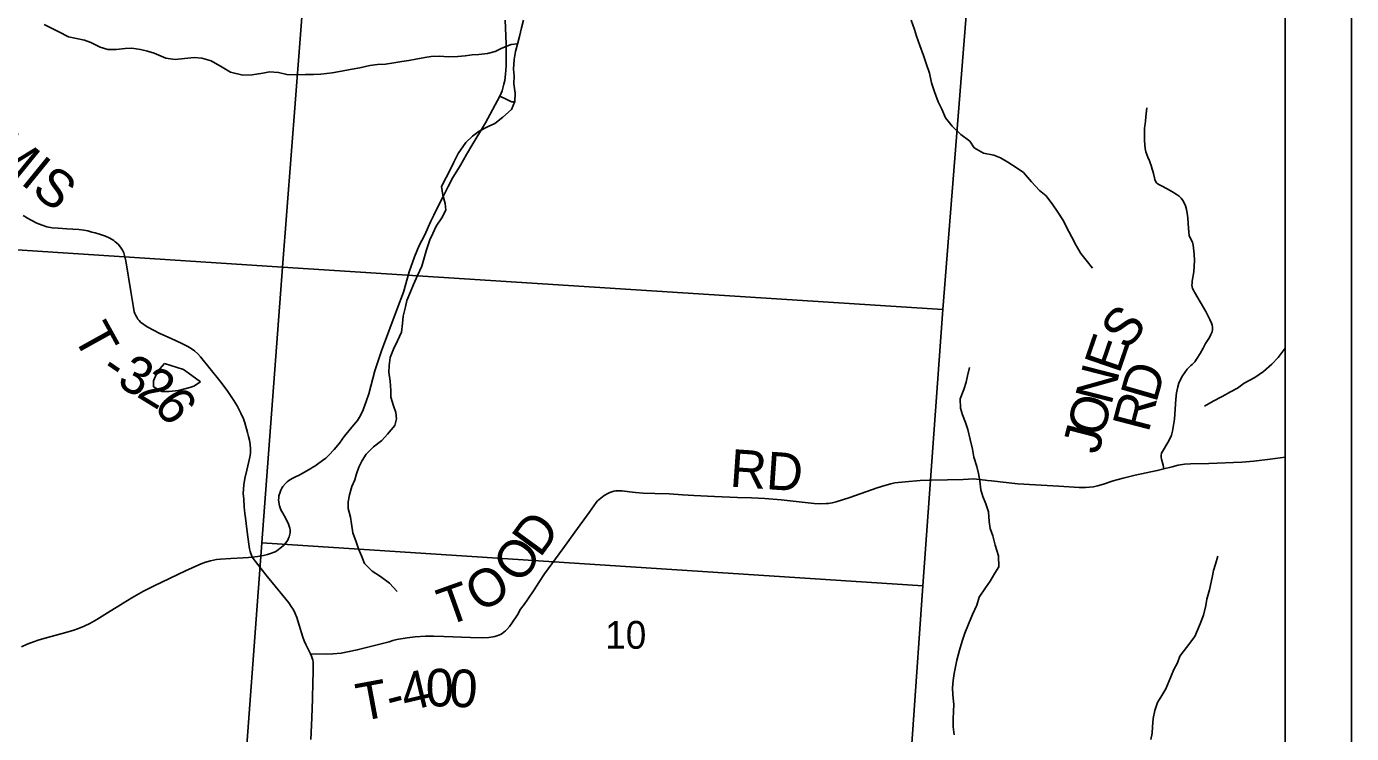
# Model space of a CAD drawing. Extents: x 0 to 34, y 0 to 22.
# Drawn here: x 6.999 to 9, y 15.952 to 17.019 of the extents above; entities that cross this region are included whole.
import ezdxf

# ---------------------------------------------------------------- set-up
doc = ezdxf.new("R2010")
doc.units = 0
for name, color, linetype in [('GM_X_Corporation', 7, 'Continuous'), ('GM_X_County_Road', 7, 'Continuous'), ('GM_X_Minor_Lake', 7, 'Continuous'), ('GM_X_Minor_River', 7, 'Continuous'), ('GM_X_Section_Text', 7, 'Continuous'), ('GM_X_Township_Road', 7, 'Continuous'), ('GM_X_Township_Road_Text', 7, 'Continuous'), ('SH_Data', 7, 'Continuous')]:
    doc.layers.add(name, color=color, linetype=linetype)

msp = doc.modelspace()

# ---------------------------------------------------------------- linework, layer by layer
at = {"layer": 'GM_X_Corporation'}
for points in [[(6.4386, 17.7441), (7.4643, 17.6703), (7.3858, 16.6558), (6.3912, 16.7203)], [(8.4629, 17.601), (8.3827, 16.5919), (7.3858, 16.6558), (7.4643, 17.6703)], [(6.3912, 16.7203), (7.3858, 16.6558), (7.3548, 16.2394), (7.3238, 15.8259), (7.3098, 15.6422), (6.7101, 15.6799), (6.3225, 15.705), (6.3352, 15.898), (6.3636, 16.3035)], [(8.3827, 16.5919), (8.3529, 16.1745), (7.3548, 16.2394), (7.3858, 16.6558)], [(8.3529, 16.1745), (8.3234, 15.756), (7.3238, 15.8259), (7.3548, 16.2394)]]:
    msp.add_lwpolyline(points, close=True, dxfattribs=at)
at = {"layer": 'GM_X_County_Road'}
msp.add_lwpolyline([(6.9919, 16.0824), (7.0002, 16.0865), (7.0098, 16.0902), (7.0186, 16.0931), (7.0365, 16.0982), (7.0533, 16.1024), (7.0694, 16.1071), (7.0781, 16.1102), (7.0866, 16.1137), (7.095, 16.1177), (7.1057, 16.1238), (7.1215, 16.1336), (7.1452, 16.1485), (7.1585, 16.1565), (7.1761, 16.1664), (7.192, 16.1744), (7.2395, 16.1973), (7.2594, 16.2062), (7.2681, 16.2095), (7.2771, 16.2122), (7.2863, 16.2142), (7.2925, 16.215), (7.308, 16.2159), (7.3266, 16.2167), (7.3347, 16.2173), (7.34, 16.2178), (7.3482, 16.2188), (7.3573, 16.2205), (7.3633, 16.2219), (7.3691, 16.2237), (7.372, 16.2248), (7.3747, 16.2261), (7.3774, 16.2276), (7.38, 16.2293), (7.3825, 16.2313), (7.3846, 16.233), (7.3876, 16.2355), (7.3905, 16.2388), (7.3937, 16.2436), (7.395, 16.2463), (7.396, 16.2486), (7.3976, 16.2546), (7.3975, 16.2589), (7.3969, 16.2618), (7.3948, 16.2676), (7.3909, 16.276), (7.3865, 16.2841), (7.3836, 16.2895), (7.3823, 16.2923), (7.3814, 16.2951), (7.3803, 16.301), (7.38, 16.3042), (7.3801, 16.3074), (7.3806, 16.3106), (7.3822, 16.316), (7.3834, 16.3191), (7.3849, 16.3219), (7.3866, 16.3245), (7.3904, 16.3292), (7.3929, 16.3314), (7.3953, 16.3334), (7.4007, 16.3367), (7.4064, 16.3396), (7.4098, 16.3413), (7.4155, 16.3441), (7.4287, 16.3519), (7.4317, 16.3537), (7.4345, 16.3554), (7.4387, 16.358), (7.4464, 16.3635), (7.4514, 16.3675), (7.4557, 16.3716), (7.4641, 16.3805), (7.4719, 16.39), (7.4792, 16.4), (7.4932, 16.4169), (7.499, 16.4242), (7.5024, 16.4293), (7.5054, 16.4345), (7.5078, 16.44), (7.5088, 16.443), (7.5098, 16.4456), (7.5127, 16.4544), (7.5163, 16.4646), (7.5251, 16.499), (7.5352, 16.5293), (7.559, 16.5928), (7.5684, 16.6177), (7.577, 16.6484), (7.5853, 16.6711), (7.5922, 16.6881), (7.6002, 16.7035), (7.61, 16.725), (7.6142, 16.7343), (7.62, 16.7457), (7.6278, 16.7611), (7.6361, 16.7775), (7.6433, 16.7907), (7.6492, 16.8004), (7.6532, 16.8071), (7.6547, 16.8097), (7.6635, 16.8258), (7.6731, 16.8417), (7.6893, 16.8685), (7.6922, 16.8736), (7.7138, 16.9138), (7.7159, 16.918), (7.7174, 16.9219), (7.7203, 16.9316), (7.7216, 16.9376), (7.7227, 16.9468), (7.7234, 16.9592), (7.7237, 16.9746), (7.7234, 16.9925), (7.7223, 17.0287)], dxfattribs=at)
at = {"layer": 'GM_X_Minor_Lake'}
for p, q in [((7.2077, 16.5101), (7.1972, 16.4979)), ((7.2362, 16.5013), (7.2077, 16.5101)), ((7.1972, 16.4979), (7.1909, 16.4842)), ((7.2488, 16.4919), (7.2362, 16.5013)), ((7.2621, 16.4826), (7.2488, 16.4919)), ((7.1909, 16.4842), (7.191, 16.4747)), ((7.191, 16.4747), (7.2039, 16.468)), ((7.2039, 16.468), (7.2149, 16.4678)), ((7.2149, 16.4678), (7.2289, 16.4694)), ((7.2289, 16.4694), (7.2459, 16.4741)), ((7.2459, 16.4741), (7.2519, 16.4761)), ((7.2519, 16.4761), (7.2621, 16.4826))]:
    msp.add_line(p, q, dxfattribs=at)
at = {"layer": 'GM_X_Minor_River'}
for p, q in [((8.3353, 17.0286), (8.34, 17.0146)), ((7.038, 17.016), (7.0258, 17.0219)), ((7.0482, 17.0108), (7.038, 17.016)), ((7.0627, 17.0033), (7.0482, 17.0108)), ((8.34, 17.0146), (8.3431, 17.0044)), ((7.0725, 17.0015), (7.0627, 17.0033)), ((7.0869, 16.9982), (7.0725, 17.0015)), ((7.0964, 16.9949), (7.0869, 16.9982)), ((7.1105, 16.9878), (7.0964, 16.9949)), ((7.1219, 16.9842), (7.1105, 16.9878)), ((7.1586, 16.986), (7.1484, 16.9855)), ((7.1714, 16.9842), (7.1586, 16.986)), ((7.717, 16.9862), (7.7069, 16.9812)), ((7.731, 16.9916), (7.717, 16.9862)), ((7.7408, 16.9927), (7.731, 16.9916)), ((8.3431, 17.0044), (8.3481, 16.9904)), ((8.3481, 16.9904), (8.3536, 16.9749)), ((7.1347, 16.9843), (7.1219, 16.9842)), ((7.1484, 16.9855), (7.1347, 16.9843)), ((7.1821, 16.9817), (7.1714, 16.9842)), ((7.1923, 16.9784), (7.1821, 16.9817)), ((7.2098, 16.9713), (7.1923, 16.9784)), ((7.2238, 16.9692), (7.2098, 16.9713)), ((7.2378, 16.9708), (7.2238, 16.9692)), ((7.2525, 16.9721), (7.2378, 16.9708)), ((7.2639, 16.971), (7.2525, 16.9721)), ((7.2783, 16.967), (7.2639, 16.971)), ((7.295, 16.9573), (7.2783, 16.967)), ((7.5659, 16.9662), (7.5538, 16.9638)), ((7.5768, 16.9678), (7.5659, 16.9662)), ((7.5874, 16.9695), (7.5768, 16.9678)), ((7.6006, 16.9722), (7.5874, 16.9695)), ((7.6104, 16.9738), (7.6006, 16.9722)), ((7.6229, 16.9743), (7.6104, 16.9738)), ((7.6362, 16.9733), (7.6229, 16.9743)), ((7.6506, 16.9738), (7.6362, 16.9733)), ((7.6619, 16.9747), (7.6506, 16.9738)), ((7.6721, 16.9759), (7.6619, 16.9747)), ((7.6823, 16.9768), (7.6721, 16.9759)), ((7.6952, 16.978), (7.6823, 16.9768)), ((7.7069, 16.9812), (7.6952, 16.978)), ((8.3536, 16.9749), (8.3578, 16.9632)), ((7.3076, 16.9498), (7.295, 16.9573)), ((7.3262, 16.9455), (7.3076, 16.9498)), ((7.3402, 16.946), (7.3262, 16.9455)), ((7.356, 16.9484), (7.3402, 16.946)), ((7.3662, 16.9504), (7.356, 16.9484)), ((7.3798, 16.9497), (7.3662, 16.9504)), ((7.3924, 16.9465), (7.3798, 16.9497)), ((7.4083, 16.9458), (7.3924, 16.9465)), ((7.4204, 16.9463), (7.4083, 16.9458)), ((7.4328, 16.9464), (7.4204, 16.9463)), ((7.4438, 16.9469), (7.4328, 16.9464)), ((7.4608, 16.949), (7.4438, 16.9469)), ((7.4748, 16.9514), (7.4608, 16.949)), ((7.488, 16.9541), (7.4748, 16.9514)), ((7.5028, 16.9566), (7.488, 16.9541)), ((7.5179, 16.9601), (7.5028, 16.9566)), ((7.5292, 16.9617), (7.5179, 16.9601)), ((7.5413, 16.9622), (7.5292, 16.9617)), ((7.5538, 16.9638), (7.5413, 16.9622)), ((8.3578, 16.9632), (8.3629, 16.9485)), ((8.3629, 16.9485), (8.366, 16.9337)), ((8.366, 16.9337), (8.3703, 16.9205)), ((8.3703, 16.9205), (8.3757, 16.905)), ((8.3757, 16.905), (8.3815, 16.8941)), ((8.3815, 16.8941), (8.3869, 16.8812)), ((8.3869, 16.8812), (8.3969, 16.8685)), ((8.3969, 16.8685), (8.4102, 16.8561)), ((8.4102, 16.8561), (8.4235, 16.8456)), ((8.4235, 16.8456), (8.4304, 16.8358)), ((8.4304, 16.8358), (8.4445, 16.8276)), ((8.4445, 16.8276), (8.4601, 16.8247)), ((8.4601, 16.8247), (8.4699, 16.8206)), ((8.4699, 16.8206), (8.481, 16.8143)), ((8.481, 16.8143), (8.495, 16.8049)), ((8.495, 16.8049), (8.5049, 16.7986)), ((8.5049, 16.7986), (8.5168, 16.7843)), ((8.5168, 16.7843), (8.529, 16.7715)), ((8.529, 16.7715), (8.5389, 16.7633)), ((8.5389, 16.7633), (8.5492, 16.7497)), ((8.5492, 16.7497), (8.5558, 16.7399)), ((8.5558, 16.7399), (8.5653, 16.7256)), ((8.5653, 16.7256), (8.5696, 16.7158)), ((8.5696, 16.7158), (8.5777, 16.7007)), ((8.5777, 16.7007), (8.5842, 16.6883)), ((8.5842, 16.6883), (8.5915, 16.6762)), ((8.5915, 16.6762), (8.5992, 16.666)), ((8.5992, 16.666), (8.6091, 16.654)), ((8.8996, 16.5331), (8.8891, 16.5194)), ((8.9, 16.5336), (8.8996, 16.5331)), ((8.8798, 16.5091), (8.867, 16.498)), ((8.8891, 16.5194), (8.8798, 16.5091)), ((8.8542, 16.4888), (8.838, 16.4807)), ((8.867, 16.498), (8.8542, 16.4888)), ((8.8173, 16.4672), (8.8045, 16.4603)), ((8.8278, 16.473), (8.8173, 16.4672)), ((8.838, 16.4807), (8.8278, 16.473)), ((8.7909, 16.4533), (8.7781, 16.446)), ((8.8045, 16.4603), (8.7909, 16.4533)), ((8.7916, 16.1976), (8.7946, 16.2071)), ((8.7946, 16.2071), (8.7983, 16.2192)), ((8.7855, 16.1683), (8.7898, 16.1873)), ((8.7898, 16.1873), (8.7916, 16.1976)), ((8.7818, 16.1546), (8.7855, 16.1683)), ((8.78, 16.1448), (8.7818, 16.1546)), ((8.7715, 16.1174), (8.7763, 16.13)), ((8.7763, 16.13), (8.78, 16.1448)), ((8.7634, 16.098), (8.7675, 16.1075)), ((8.7675, 16.1075), (8.7715, 16.1174)), ((8.751, 16.0816), (8.7634, 16.098)), ((8.7372, 16.0584), (8.7409, 16.0686)), ((8.7409, 16.0686), (8.751, 16.0816)), ((8.7272, 16.0374), (8.7316, 16.0481)), ((8.7316, 16.0481), (8.7372, 16.0584)), ((8.7198, 16.0192), (8.7272, 16.0374)), ((8.7071, 15.9986), (8.7138, 16.0089)), ((8.7138, 16.0089), (8.7198, 16.0192)), ((8.7005, 15.9743), (8.703, 15.9861)), ((8.703, 15.9861), (8.7071, 15.9986)), ((8.6995, 15.9618), (8.7005, 15.9743)), ((8.697, 15.9424), (8.6988, 15.9523)), ((8.6988, 15.9523), (8.6995, 15.9618))]:
    msp.add_line(p, q, dxfattribs=at)
for points in [[(7.7496, 17.0285), (7.7467, 17.0171), (7.7438, 17.0038), (7.7412, 16.9943), (7.7379, 16.9814), (7.7357, 16.9689), (7.7347, 16.9545), (7.7356, 16.9443), (7.7353, 16.9321), (7.7373, 16.9185), (7.7367, 16.9056), (7.7318, 16.8935), (7.7187, 16.882), (7.7063, 16.8724), (7.6965, 16.8681), (7.6826, 16.8608), (7.6728, 16.8531), (7.6627, 16.8436), (7.6511, 16.8272), (7.6444, 16.8142), (7.6399, 16.8043), (7.6328, 16.791), (7.6262, 16.7773), (7.6278, 16.7641), (7.6317, 16.7516), (7.6325, 16.7417), (7.6266, 16.7303), (7.618, 16.7177), (7.6131, 16.7063), (7.6083, 16.6968), (7.6031, 16.6816), (7.5995, 16.6675), (7.5962, 16.6573), (7.5895, 16.6432), (7.5835, 16.6295), (7.5791, 16.6185), (7.5735, 16.6055), (7.5714, 16.5957), (7.5681, 16.5816), (7.567, 16.5703), (7.5656, 16.5574), (7.5593, 16.5444), (7.5534, 16.5319), (7.5486, 16.5193), (7.5468, 16.5072), (7.5465, 16.4973), (7.5485, 16.4837)], [(8.4003, 15.9496), (8.3987, 15.9617), (8.3986, 15.9731), (8.3992, 15.9852), (8.3995, 15.9954), (8.3979, 16.0102), (8.3974, 16.0204), (8.3984, 16.0318), (8.3999, 16.0424), (8.402, 16.0523), (8.4039, 16.0625), (8.4079, 16.0773), (8.4119, 16.091), (8.416, 16.1032), (8.4215, 16.1169), (8.4275, 16.1313), (8.4342, 16.1454), (8.4378, 16.1572), (8.4476, 16.1713), (8.4543, 16.1816), (8.4617, 16.1934), (8.4673, 16.2033), (8.4668, 16.22), (8.4618, 16.2358), (8.4582, 16.2498), (8.4543, 16.2612), (8.4531, 16.2714), (8.4519, 16.2862), (8.448, 16.2982), (8.4433, 16.3096), (8.4402, 16.3194), (8.4386, 16.333), (8.437, 16.344), (8.4342, 16.3546), (8.4296, 16.3686), (8.4276, 16.381), (8.424, 16.3954), (8.4209, 16.4105), (8.417, 16.4211), (8.4127, 16.4328), (8.4096, 16.4427), (8.4091, 16.457), (8.4147, 16.4711), (8.4184, 16.4818), (8.4202, 16.4916), (8.4231, 16.5042)], [(7.5485, 16.4837), (7.5494, 16.4693), (7.5495, 16.4594), (7.5534, 16.4462), (7.5568, 16.4364), (7.5581, 16.4266), (7.5555, 16.4167), (7.5446, 16.4037), (7.536, 16.3938), (7.5232, 16.3842), (7.5124, 16.3735), (7.506, 16.3636), (7.5012, 16.3537), (7.4975, 16.3438), (7.4949, 16.3343), (7.4908, 16.3244), (7.4868, 16.3118), (7.485, 16.3012), (7.4851, 16.2914), (7.4886, 16.2781), (7.4902, 16.2679), (7.4922, 16.2547), (7.4969, 16.2411), (7.5007, 16.2305), (7.505, 16.2199), (7.5096, 16.2082), (7.5211, 16.1966), (7.534, 16.1887), (7.5474, 16.1783), (7.5592, 16.1659)]]:
    msp.add_lwpolyline(points, dxfattribs=at)
at = {"layer": 'GM_X_Township_Road'}
for points in [[(7.736, 16.9052), (7.7336, 16.9052), (7.7321, 16.9054), (7.7306, 16.9058), (7.7277, 16.907), (7.7234, 16.909), (7.7138, 16.9138)], [(8.7596, 16.5088), (8.7633, 16.5129), (8.7672, 16.5184), (8.7714, 16.5254), (8.7758, 16.5334), (8.7798, 16.5405), (8.7854, 16.5496), (8.7877, 16.554), (8.7894, 16.558), (8.7901, 16.5613), (8.7901, 16.5648), (8.7894, 16.568), (8.7884, 16.5712), (8.7862, 16.5768), (8.7836, 16.5818), (8.78, 16.5885), (8.7629, 16.618), (8.7612, 16.6208), (8.7599, 16.6234), (8.7592, 16.6259), (8.759, 16.6286), (8.7593, 16.6316), (8.7596, 16.6344), (8.7617, 16.6483), (8.7626, 16.6573), (8.7627, 16.6658), (8.7622, 16.6751), (8.7609, 16.6889), (8.76, 16.6931), (8.7568, 16.6987), (8.755, 16.7035), (8.7543, 16.7083), (8.7535, 16.7213), (8.7531, 16.7303), (8.7521, 16.7371), (8.7509, 16.7425), (8.7492, 16.7481), (8.7474, 16.7526), (8.7453, 16.7564), (8.7428, 16.7599), (8.7397, 16.7628), (8.7352, 16.766), (8.7285, 16.77), (8.7209, 16.7741), (8.714, 16.7777), (8.7082, 16.7808), (8.7058, 16.7831), (8.7043, 16.7852), (8.7031, 16.7879), (8.7023, 16.7906), (8.7008, 16.7969), (8.6999, 16.8005), (8.699, 16.8037), (8.6974, 16.809), (8.696, 16.813), (8.6949, 16.8162), (8.6924, 16.8215), (8.6908, 16.8257), (8.6896, 16.8297), (8.6887, 16.8348), (8.6879, 16.8402), (8.6874, 16.8468), (8.6873, 16.8536), (8.6874, 16.8599), (8.6876, 16.8651), (8.6879, 16.869), (8.6883, 16.8722), (8.6888, 16.8759), (8.6897, 16.8823), (8.6911, 16.896)], [(7.34, 16.2178), (7.3369, 16.2262), (7.3363, 16.2302), (7.3331, 16.2521), (7.331, 16.2685), (7.3299, 16.277), (7.329, 16.2836), (7.328, 16.294), (7.3273, 16.3054), (7.3267, 16.3141), (7.3269, 16.3204), (7.3276, 16.3268), (7.3292, 16.3368), (7.3322, 16.3491), (7.3367, 16.3688), (7.3375, 16.3749), (7.3376, 16.3815), (7.337, 16.388), (7.336, 16.3945), (7.3347, 16.4002), (7.3332, 16.406), (7.3289, 16.4208), (7.3268, 16.4266), (7.323, 16.4351), (7.3173, 16.4461), (7.3123, 16.4543), (7.3023, 16.4693), (7.2912, 16.4841), (7.2621, 16.5204), (7.2578, 16.5249), (7.2532, 16.5291), (7.2482, 16.5327), (7.2429, 16.5359), (7.2318, 16.5415), (7.2177, 16.5479), (7.2006, 16.5554), (7.1814, 16.5654), (7.1763, 16.5689), (7.1715, 16.5728), (7.1693, 16.575), (7.1674, 16.5773), (7.1657, 16.5799), (7.1642, 16.5826), (7.163, 16.5854), (7.1621, 16.5884), (7.1603, 16.5976), (7.1569, 16.619), (7.1494, 16.6653), (7.1473, 16.6734), (7.1462, 16.6771), (7.1441, 16.6813), (7.1411, 16.6859), (7.1376, 16.6902), (7.1334, 16.6939), (7.1311, 16.6958), (7.1286, 16.6975), (7.124, 16.6999), (7.1184, 16.7024), (7.1127, 16.7043), (7.1028, 16.7072), (7.0981, 16.7085), (7.0919, 16.7102), (7.0859, 16.7114), (7.0783, 16.7124), (7.0603, 16.7135), (7.0472, 16.7143), (7.0381, 16.7152), (7.03, 16.7167), (7.0231, 16.7188), (7.015, 16.7218), (7.0062, 16.7265), (7.0007, 16.7294), (6.9943, 16.7335)], [(8.7167, 16.3512), (8.7155, 16.3567), (8.7131, 16.3656), (8.7125, 16.3687), (8.7125, 16.3718), (8.7133, 16.3747), (8.7147, 16.3775), (8.7228, 16.3907), (8.7257, 16.3962), (8.728, 16.4019), (8.7298, 16.4079), (8.7308, 16.414), (8.7325, 16.426), (8.7346, 16.4565), (8.7358, 16.4658), (8.7376, 16.4747), (8.7393, 16.4805), (8.7417, 16.4862), (8.7447, 16.4916), (8.7482, 16.4966), (8.7521, 16.5014), (8.7549, 16.5044), (8.7574, 16.507), (8.7596, 16.5088)], [(7.4284, 16.0718), (7.4529, 16.0713), (7.4621, 16.0718), (7.4744, 16.0731), (7.4866, 16.0752), (7.4987, 16.0778), (7.5468, 16.0901), (7.5527, 16.0919), (7.5587, 16.0933), (7.5739, 16.0959), (7.5862, 16.0975), (7.6016, 16.0984), (7.6139, 16.0985), (7.6294, 16.0982), (7.6697, 16.0964), (7.6882, 16.0961), (7.6975, 16.0965), (7.7036, 16.0973), (7.7065, 16.0979), (7.7094, 16.0989), (7.7123, 16.1), (7.715, 16.1012), (7.7176, 16.1027), (7.7202, 16.1044), (7.7225, 16.1064), (7.7247, 16.1084), (7.7287, 16.113), (7.7323, 16.118), (7.7405, 16.1309), (7.7455, 16.1391), (7.7509, 16.1465), (7.7562, 16.1542), (7.7659, 16.1686), (7.7728, 16.1797), (7.7817, 16.1926), (7.8091, 16.2304), (7.8271, 16.2557), (7.8488, 16.2854), (7.8559, 16.2955), (7.8597, 16.3004), (7.8617, 16.3028), (7.864, 16.305), (7.8664, 16.3071), (7.8689, 16.3091), (7.8716, 16.3109), (7.8772, 16.314), (7.8801, 16.3153), (7.883, 16.3163), (7.886, 16.3172), (7.8892, 16.3177), (7.8924, 16.3179), (7.8986, 16.3178), (7.9096, 16.3164), (7.9191, 16.3154), (7.9303, 16.3145), (7.9482, 16.314), (7.9696, 16.3133), (7.9899, 16.312), (8.0071, 16.3108), (8.0384, 16.3092), (8.0727, 16.308), (8.0938, 16.3075), (8.114, 16.3066), (8.1389, 16.3042), (8.1886, 16.2988), (8.1978, 16.2984), (8.207, 16.2987), (8.21, 16.2988), (8.216, 16.2998), (8.222, 16.3012), (8.2426, 16.3079), (8.2836, 16.3223), (8.2955, 16.3262), (8.3046, 16.3286), (8.3107, 16.3298), (8.3261, 16.3317), (8.3488, 16.3337), (8.363, 16.334), (8.3902, 16.3346), (8.4137, 16.3352), (8.4296, 16.3358), (8.4421, 16.3347), (8.4471, 16.3341), (8.4506, 16.3337), (8.4562, 16.333), (8.496, 16.3286), (8.558, 16.3248), (8.589, 16.3231), (8.5983, 16.323), (8.6044, 16.3233), (8.6105, 16.3241), (8.6165, 16.3255), (8.6254, 16.3281), (8.6402, 16.3329), (8.6552, 16.3371), (8.6734, 16.3414), (8.7067, 16.3484), (8.7167, 16.3512), (8.7294, 16.3544), (8.7384, 16.3565), (8.7476, 16.358), (8.7568, 16.3585), (8.7847, 16.359), (8.8342, 16.3612), (8.8527, 16.3627), (8.8773, 16.3655), (8.9, 16.3687)], [(7.4287, 15.9423), (7.43, 15.9753), (7.4311, 16.0041), (7.4315, 16.0289), (7.4321, 16.0436), (7.4323, 16.056), (7.432, 16.0591), (7.4315, 16.0621), (7.4309, 16.0651), (7.4299, 16.0681), (7.4284, 16.0718), (7.4212, 16.0861), (7.4186, 16.0916), (7.4165, 16.0972), (7.4113, 16.115), (7.4075, 16.1268), (7.4051, 16.1326), (7.4023, 16.1382), (7.3991, 16.1435), (7.3955, 16.1487), (7.3864, 16.16), (7.3632, 16.1879), (7.3536, 16.2), (7.34, 16.2178)]]:
    msp.add_lwpolyline(points, dxfattribs=at)
at = {"layer": 'SH_Data'}
for p, q in [((9, 21), (9, 14)), ((8.9, 20.9), (8.9, 14.1))]:
    msp.add_line(p, q, dxfattribs=at)

# ---------------------------------------------------------------- texts
at = {"layer": 'GM_X_Section_Text'}
msp.add_text('10', height=0.04186, rotation=0, dxfattribs=at).set_placement((7.873, 16.0796))
at = {"layer": 'GM_X_Township_Road_Text'}
for s, height, rotation, p in [('LOOMIS', 0.05682, 320.8393, (6.8152, 16.924)), ('S', 0.0568, 49.3822, (8.6602, 16.5285)), ('T', 0.0568, 299.0209, (7.0686, 16.5521)), ('E', 0.0568, 71.0568, (8.6492, 16.4932)), ('-', 0.0568, 325.4317, (7.1082, 16.494)), ('3', 0.0568, 332.3256, (7.1338, 16.4769)), ('N', 0.0568, 75.5632, (8.6371, 16.4459)), ('D', 0.0568, 73.9825, (8.705, 16.4493)), ('2', 0.0568, 328.4106, (7.1639, 16.4612)), ('6', 0.0568, 307.3268, (7.1897, 16.4465)), ('O', 0.0568, 75.5529, (8.6246, 16.3975)), ('R', 0.0568, 75.4336, (8.6934, 16.4045)), ('J', 0.0568, 75.5579, (8.6179, 16.3716)), ('RD', 0.05682, 356.0553, (8.0603, 16.3244)), ('D', 0.0568, 53.8521, (7.7747, 16.2156)), ('O', 0.0568, 54.0332, (7.7454, 16.1751)), ('O', 0.0568, 30.9231, (7.6841, 16.1327)), ('T', 0.0568, 19.625, (7.6331, 16.1132)), ('4', 0.0568, 13.2411, (7.5717, 15.9844)), ('0', 0.0568, 0.9212, (7.6026, 15.9921)), ('0', 0.0568, 356.6782, (7.6365, 15.9926)), ('T', 0.0568, 10.5333, (7.5033, 15.9698)), ('-', 0.0568, 14.791, (7.5495, 15.9786))]:
    msp.add_text(s, height=height, rotation=rotation, dxfattribs=at).set_placement(p)

doc.saveas('drawing.dxf')
